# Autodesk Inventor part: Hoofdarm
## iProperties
Created: 2007-06
Part Number: Hoofdarm
Material: Steel
Document SubType Name: Modeling
Designer: Phil Trethewie
Author: Phil Trethewie
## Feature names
1. Sweep1
